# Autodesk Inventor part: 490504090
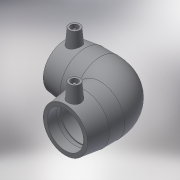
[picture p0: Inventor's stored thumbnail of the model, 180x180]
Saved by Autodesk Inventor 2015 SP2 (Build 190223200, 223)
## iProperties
Created: 2017-06
Part Number: 490504090
Material: Generic
Description: PLASSON 90° ELBOW 90
Document SubType Name: Modeling
Designer: KIM
Mass: 55.0731 g
Surface Area: 148.067 cm^2
Volume: 55.0731 cm^3
Density: 1 g/cm^3
Appearance: Default
Author: KIM
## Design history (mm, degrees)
derived "490504.ipt"
feature "Solid1::490504.ipt"
tag "TaggingFeature1"
body "Solid1"
other parameters: "d2" = 113, "d4" = 53.25, "d5" = 101.7, "d8" = 168 deg, "d10" = 31.2, "d11" = 10.4, "d14" = 17.6296, "d19" = 3.52592, "d20" = 168 deg, "d22" = 103.96, "d23" = 113, "d24" = 100.8412, "d29" = 69, "d30" = 15, "d31" = 74.55, "d34" = 5 deg, "d35" = 15, "d39" = 5 deg, "d41" = 4, "d42" = 14, "d43" = 0, "d45" = 4, "d46" = 14, "d47" = 0, "d50" = 76.5, "d51" = 31.2, "d52" = 78, "d54" = 90 deg, "d67" = 45 deg, "d71" = 90 deg, "d75" = 5.65, "d82" = 45 deg, "d83" = 78, "d84" = 101.7, "d86" = 50.85, "d87" = 90 deg, "d90" = 78, "d91" = 0, "d92" = 78, "d93" = 0, "d94" = 90 deg, "d95" = 51.98, "d98" = 213, "d101" = 3, "d102" = 0, "d103" = 3, "d104" = 0, "d105" = 22.62, "d106" = 5.655, "d107" = 213, "d110" = 42.9, "L_" = 213, "L_1" = 78, "D_" = 113, "A_" = 69, "d_2" = 12
